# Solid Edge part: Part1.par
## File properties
Author: Deepak Maini
Template: normal.par
Last saved by: CADCIM
Revision: 4
Application: Solid Edge
Accuracy: 0.99
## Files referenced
..\Asm2.asm
=D:\sld-edg-15\cd-models\c09-sld-edg-15\figure9-11&12\Asm2.asm
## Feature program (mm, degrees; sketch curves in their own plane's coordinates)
sketch for "unnamed Protrusion 1" #1 plane through (0, 0, 0) normal (0, 0, 1) x-axis (1, 0, 0)
  line (-53.424, 13.2886) -> (-4.9489, 23.498)
  arc centre (0, 0) radius 24.0135 from (-4.9489, 23.498) to (4.9424, 23.4994) cw
  line (4.9424, 23.4994) -> (57.7581, 12.3911)
  arc centre (55.152, 0) radius 12.6622 from (57.7581, 12.3911) to (57.7581, -12.3911) cw
  line (57.7581, -12.3911) -> (4.9424, -23.4994)
  arc centre (0, 0) radius 24.0135 from (4.9424, -23.4994) to (-4.9489, -23.498) cw
  line (-53.424, -13.2886) -> (-4.9489, -23.498)
  arc centre (-50.6253, 0) radius 13.5802 from (-53.424, -13.2886) to (-53.424, 13.2886) cw
sketch for "unnamed Protrusion 1" #2 plane through (0, 0, 0) normal (0, 0, 1) x-axis (1, 0, 0)
  circle centre (-50.6253, 0) radius 7
sketch for "unnamed Protrusion 1" #3 plane through (0, 0, 0) normal (0, 0, 1) x-axis (1, 0, 0)
  circle centre (54.576, 0) radius 7
extrude "unnamed Protrusion 1" add finite 12.7 symmetric
sketch for "ExtrudedProtrusion_2" plane through (1.8044, 0, 12.7) normal (0, 0, 1) x-axis (0.97859, 0.205819, 0)
  circle centre (-1.7657, 0.3714) radius 14.0039
extrude "ExtrudedProtrusion_2" add through along -normal  Plane_Distance = 6.35 mm
sketch for "unnamed Hole 1" plane through (0, 0, 12.7) normal (0, 0, 1) x-axis (0, 1, 0)
  hole centre (0, 0) bore radius 9
hole "unnamed Hole 1" through
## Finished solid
Body 1: solid body, 15 faces, 32 edges, 16 vertices.
  Faces by surface: cylinder 8, plane 7
  Edges by curve: circle 16, line 16
Bounding box of the edges (mm): 132.020 x 48.027 x 19.050, from (-64.2054, -24.0135, -6.35) to (67.8142, 24.0135, 12.7).
Cylindrical faces by radius (mm): R7 x2, R9 x1, R12.6622 x1, R13.5802 x1, R14.0039 x1, R24.0135 x2
Planar faces by outward normal: +z 2, -z 1, oblique 4
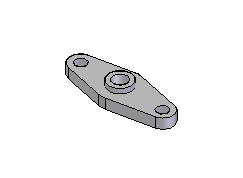
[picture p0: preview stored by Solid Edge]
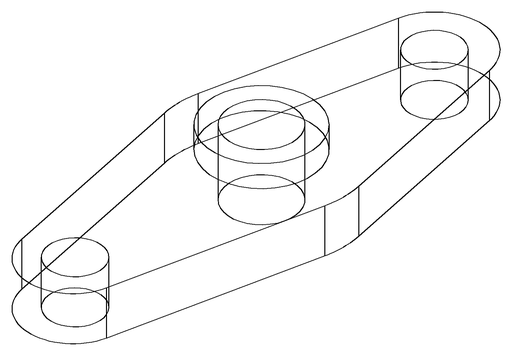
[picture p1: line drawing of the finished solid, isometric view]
